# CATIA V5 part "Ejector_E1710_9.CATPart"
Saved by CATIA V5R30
Part number: Vyhazovac_2.5x160_7
Nomenclature: E1710/2.5x160
Description: MEUSBURGER
Property "Material": "1.221"
Publications: "__DrillHole", "Base"
Bounding box of the stored display mesh (mm): x -2.499 to 2.499, y -2.499 to 2.499, z 0 to 152
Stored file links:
  E:\Bakalarka\Model\Forma_v7\Ejector_E1710_9.CATPart
  E:\dev\MoldDesign\intel_a\startup\components\MoldCatalog\Ejector\Meusburger\Ejector_E1710\TableE1710.txt
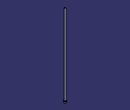
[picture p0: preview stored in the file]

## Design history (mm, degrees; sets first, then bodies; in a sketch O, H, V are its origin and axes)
Parameters
  Ref = "E1710/2.5x160" {design table}
  D1 = 2.5 mm {design table}
  D3 = 5 mm {design table}
  L = 160 mm {design table}
  L3 = 2 mm {design table}
  R = 0.3 mm {design table}
  k_d3 = 6 mm {design table}
  k_d1 = 2.7 mm {design table}
  k_F = 0.3 mm {design table}
  kl = 17 mm {design table}
  Mat = "1.221" {design table}
  HeatTreat = "ISO6751" {design table}
  Offset_Parting = 10 mm
  Anti_Rotation = "Normal"
  Anti_Rotation_D = 1.55 mm
  Anti_Rotation_D_Icut = 1.55 mm
  Add_Length_L = 0.0877 mm
  Add_Length_D3 = 0 mm
  SupplierRef = "Meusburger 2017"
  BmpRef = "F_MldEjectorD1"
  DrillHole_Length = 225 mm
  ValidationTest = false
  Anti_Rotation_D_min = 1.55 mm {= OffSet_D1 /2}
  Anti_Rotation_D_max = 2.425 mm {= D3/2-0.075mm}
  Anti_Rotation_D_ref = 1.55 mm {= Anti_Rotation_D}
  Anti_Rotation_D_Icut_ref = 1.55 mm {= Anti_Rotation_D_Icut}
  Anti_Rotation_Ref_Icut = 2.3246 mm
  Offset_L = 20 mm
  D = 2.5 mm {= D1}
  OffSet_D1 = 3.1 mm {= D1+2*R}
  OffSet_D3 = 6 mm {= D3+1mm}
  XG_Split = 150 mm
  YG_Split = 15 mm
  ZG_Split = -198 mm
  DirX_Split = 0 mm
  DirY_Split = 0 mm
  DirZ_Split = 1 mm
Set1 "BaseBody"
  Point1 "Base": (0, 0, 0)
  Plane1: type Offset, RefPlane xy-plane, Offset 225 {= DrillHole_Length}, reversed
  Sketch1 "Sketch.2" on xy-plane, origin (0, 0, 0), H (1, 0, 0), V (0, 1, 0)
    point P1 (-0.46, 1.1623)
    point P2 (0.46, 1.1623)
    construction line L1 (-0.46, 1.1623) -> (0.46, 1.1623)
    point P3 (0.46, -1.1623)
    line L2 (0.46, -1.1623) -> (0.46, 1.1623)
    point P4 (-0.46, -1.1623)
    construction line L3 (0.46, -1.1623) -> (-0.46, -1.1623)
    line L4 (-0.46, 1.1623) -> (-0.46, -1.1623)
    point P5 (-0.21, 1.1623)
    arc A1 centre (-0.21, 1.1623) radius 0.25 from (-0.21, 1.4123) to (-0.46, 1.1623) ccw
    point P7 (0.21, 1.1623)
    point P8 (0.21, 1.4123)
    arc A2 centre (0.21, 1.1623) radius 0.25 from (0.46, 1.1623) to (0.21, 1.4123) ccw
    line L5 (-0.21, 1.4123) -> (0.21, 1.4123)
    point P9 (-0.46, -1.1623)
    arc A3 centre (-0.21, -1.1623) radius 0.25 from (-0.46, -1.1623) to (-0.21, -1.4123) ccw
    point P11 (0.21, -1.4123)
    line L6 (-0.21, -1.4123) -> (0.21, -1.4123)
    point P12 (0.46, -1.1623)
    arc A4 centre (0.21, -1.1623) radius 0.25 from (0.21, -1.4123) to (0.46, -1.1623) ccw
    point P14 (-0.46, 1.1623)
    point P15 (-0.46, -1.1623)
    point P16 (0.46, 1.1623)
    point P17 (0.46, -1.1623)
    reference projected circle E1 centre (0, 0) radius 1.25 from edge [face of Shaft1 from Sketch2.L3 | face of Shaft1 from Sketch2.L4]
    reference projected circle E2 centre (0, 0) radius 1.25 from edge [face of Shaft1 from Sketch2.L3 | face of Shaft1 from Sketch2.L4]
    reference projected circle E3 centre (0, 0) radius 1.25 from edge [face of Shaft1 from Sketch2.L3 | face of Shaft1 from Sketch2.L4]
    reference projected circle E4 centre (0, 0) radius 1.25 from edge [face of Shaft1 from Sketch2.L3 | face of Shaft1 from Sketch2.L4]
    point P18 (-0.46, -1.1623)
    point P19 (-0.21, -1.4123)
    point P20 (0.21, -1.4123)
    point P21 (0.46, -1.1623)
    point P22 (-0.21, -1.4123)
    point P23 (0.21, -1.4123)
    distance P14 P15 = 2.3246 (reference)
    distance P16 P17 = 2.3246 (reference)
    distance L1 P14 = 0 (reference)
    radius A1 = 1.25
    distance L4 V = 1.56
    distance L2 V = 2.435
    distance L5 L6 = 5
    horizontal: L1 H, L3 H, L5 H
    vertical: L2 V, L4 V
    coincidence: P5 L1, P7 L1, P3 P12, P14 L4, P15 L4, P16 L2, P17 L2, P14 E1, P15 E2, P16 E3, P17 E4, P3 P21, P4 P18, P20 P23, P19 P22
    tangency: A1 L4, A2 L2, A2 L5, A1 L5
    symmetry: P1 P9 H, A1 A3 H, P8 P11 H, L5 L6 H, P2 P12 H, A2 A4 H
  DatumSurface1
Body1 "PartBody" (main body)
  Sketch2 "Sketch.1" on zx-plane, origin (0, 0, 0), H (-1, 0, 0), V (0, 0, 1)
    point P1 (0, 160)
    line L1 (1.25, 160) -> (0, 160)
    line L2 (1.25, 2) -> (1.25, 160)
    line L3 (2.5, 2) -> (1.25, 2)
    line L4 (2.5, 0) -> (2.5, 2)
    point P5 (0, 0)
    line L5 (0, 0) -> (2.5, 0)
    point P6 (0, 160)
    axis line L6 (0, 160) -> (0, 0)
    point P7 (0, 0)
    point P8 (1.25, 2)
    point P9 (1.25, 2)
    line L7 (0, 160) -> (0, 0)
    distance L5 L3 = 2 {= L3}
    distance L5 L1 = 160 {= L}
    distance L2 L6 = 1.25 {= D1 /2}
    distance L4 L6 = 2.5 {= D3 /2}
    coincidence: L6 P5, P1 L6, L5 H, L6 V, P7 O, P6 P1, P8 P9
    vertical: L2 V, L7 V
    horizontal: L1 H
  Shaft1 "Shaft.1": profile Sketch2, axis Sketch2.L6, angle 360
  Pocket1 "Pocket.1": profile Sketch1, direction (0, 0, 1), length 3, outer side, deactivated
  Pocket2 "Pocket.2": profile Sketch1, direction (0, 0, 1), length 3, outer side, deactivated
  Fillet1: radius 0.3 {= R}, on edge [face of Shaft1 from Sketch2.L2 | face of Shaft1 from Sketch2.L3]
  Pocket3: profile face of Shaft1 from Sketch2.L1, direction along face of Shaft1 from Sketch2.L1 reversed, up to face of DatumSurface1
Body2 "__DrillHole"
  Sketch3 "Sketch.3" on face of Shaft1, origin (0, 0, 0), H (1, 0, 0), V (0, -1, 0)
    point P1 (0, 0)
    reference projected point E1 (0, 0) from Point1
    coincidence: E1 P1
  Hole1 "Hole.1": placed by Sketch3, at (0, 0, 0) direction (0, 0, 1), diameter 3.1 {= OffSet_D1}, depth 140 {= L-Offset_L}
  Sketch4 "Sketch.4" on face of Shaft1, origin (0, 0, 0), H (1, 0, 0), V (0, -1, 0)
    point P1 (0, 0)
    reference projected point E1 (0, 0) from Point1
    coincidence: E1 P1
  Hole2 "Hole.2": placed by Sketch4, at (0, 0, 0) direction (0, 0, 1), diameter 2.5 {= D1}, depth 160 {= L}
  Sketch5 "Sketch.5" on face of Shaft1 from Sketch2.L3, origin (0, 0, 2), H (1, 0, 0), V (0, 1, 0)
    point P1 (0, 0)
    reference projected point E1 (0, 0) from Point1
    coincidence: E1 P1
  Hole3 "Hole.3": placed by Sketch5, at (0, 0, 2) direction (0, 0, -1), diameter 6 {= OffSet_D3}, depth 227 {= L3 +DrillHole_Length}
  Chamfer1: length 0.3 {= k_F}, angle 45, on edge [face of Hole1 | face of Hole3]
  Body3 "__Body.1"
    Pocket4 "Pocket.3": profile Sketch1, direction (0, 0, -1), length 225, opposite side length 2, deactivated
  Assemble1: tool Body3
  Chamfer2: length 0.3 {= k_F}, angle 45, on edge [start face of Pocket4 | face of Hole1], deactivated
  Body4 "__Body.2"
    Pocket5 "Pocket.4": profile Sketch1, direction (0, 0, -1), length 225, opposite side length 2, deactivated
  Assemble2: tool Body4
  Chamfer3: length 0.3 {= k_F}, angle 45, on edge [start face of Pocket5 | face of Hole1], deactivated
Relations
  design table "TableE1710", configuration 134, drives Ref, D1, D3, L, L3, R, k_d3, k_d1, k_F, kl, Mat, HeatTreat
  Offset_L = 20mm (deactivated)
  rule "Cut_Head_rule":
    let sketch_cut (length)
    let PartBody_Pocket_Sketch (Boolean)
    let I_PartBody_Pocket (Boolean)
    let D_PartBody_Pocket (Boolean)
    let N_DrillHole_Hole (Boolean)
    let N_DrillHole_Hole_Sketch (Boolean)
    let I_DrillHole_Pocket (Boolean)
    let D_DrillHole_Pocket (Boolean)
    /* --------------------------------------------------------------------------------------*/
    if Anti_Rotation =="Normal"
    {
    	sketch_cut=Anti_Rotation_D_max
    	PartBody_Pocket_Sketch = false
    	I_PartBody_Pocket = false
    	D_PartBody_Pocket = false
    	N_DrillHole_Hole = true
    	N_DrillHole_Hole_Sketch = true
    	I_DrillHole_Pocket = false
    	D_DrillHole_Pocket = false
    	Chamfer1.Activity= true
    	Chamfer2.Activity= false
    	Chamfer3.Activity= false
    }
    if Anti_Rotation == "I_Cut"
    {
    	sketch_cut=Anti_Rotation_D_Icut_ref
    	PartBody_Pocket_Sketch = true
    	I_PartBody_Pocket = true
    	D_PartBody_Pocket = false
    	N_DrillHole_Hole = false
    	N_DrillHole_Hole_Sketch = false
    	I_DrillHole_Pocket = true
    	D_DrillHole_Pocket = false
    	Chamfer1.Activity= false
    	Chamfer2.Activity= true
    	Chamfer3.Activity= false
    }
    if Anti_Rotation =="D_Cut"
    {
    	sketch_cut=Anti_Rotation_D_max
    	PartBody_Pocket_Sketch = true
    	I_PartBody_Pocket = false
    	D_PartBody_Pocket = true
    	N_DrillHole_Hole = false
    	N_DrillHole_Hole_Sketch = false
    	I_DrillHole_Pocket = false
    	D_DrillHole_Pocket = true
    	Chamfer1.Activity= false
    	Chamfer2.Activity= false
    	Chamfer3.Activity= true
    }
    /* --------------------------------------------------------------------------------------*/
    Sketch1.distance(L2 V) = sketch_cut+0.01mm
    Sketch1.distance(L4 V) =Anti_Rotation_D_ref+0.01mm
    Sketch1.radius(A1) =D/2
    Pocket4.FirstLimit.Depth = DrillHole_Length
    Pocket5.FirstLimit.Depth = DrillHole_Length
    Pocket1.FirstLimit.Depth = L3+1mm
    Pocket2.FirstLimit.Depth = L3+1mm
    Pocket4.SecondLimit.Depth = L3
    Pocket5.SecondLimit.Depth =L3
    Pocket1.Activity = I_PartBody_Pocket
    Pocket2.Activity = D_PartBody_Pocket
    Sketch1.Activity =PartBody_Pocket_Sketch
    Hole3.Activity= N_DrillHole_Hole
    Sketch5.Activity = N_DrillHole_Hole_Sketch
    Pocket4.Activity = I_DrillHole_Pocket
    Pocket5.Activity  = D_DrillHole_Pocket
  rule "Anti_Rotation_Icut_constrain":
    let Ref1(length)
    let Ref2(length)
    let Ref3(length)
    let Diam1(length)
    let Diam2(length)
    let Add_Length_Lmin (length)
    Ref1=Sketch1.distance(P14 P15)
    Ref2=Sketch1.distance(P16 P17)
    Diam1=D
    Diam2=D3
    /* --------------------------------------------------------------------*/
    if Ref1 >Ref2
    	Anti_Rotation_Ref_Icut = Ref1
    else
    	Anti_Rotation_Ref_Icut  =Ref2
    Add_Length_D3 .InferiorRange=Anti_Rotation_Ref_Icut /2+Diam1/2 -Diam2/2
    if Add_Length_D3 .InferiorRange<0mm
    	Add_Length_D3 .InferiorRange=0mm
    if ValidationTest == "true"
    	Ref3   = 2*Add_Length_L +Anti_Rotation_Ref_Icut  +2*Diam1/2
    else
    	Ref3  =Diam2+2*Add_Length_D3
    if Ref3 <Diam2
    {
    	Ref3 =Diam2
    }
    /* --------------------------------------------------------------------*/
    Sketch1.distance(L5 L6) = Ref3
    Add_Length_L .InferiorRange=Diam2/2-Anti_Rotation_Ref_Icut/2-Diam1/2
    Add_Length_Lmin=Diam2/2-Anti_Rotation_Ref_Icut/2-Diam1/2
    if Add_Length_Lmin<0mm
    	Add_Length_L .InferiorRange=0mm
    else
    	Add_Length_L .InferiorRange=Add_Length_Lmin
